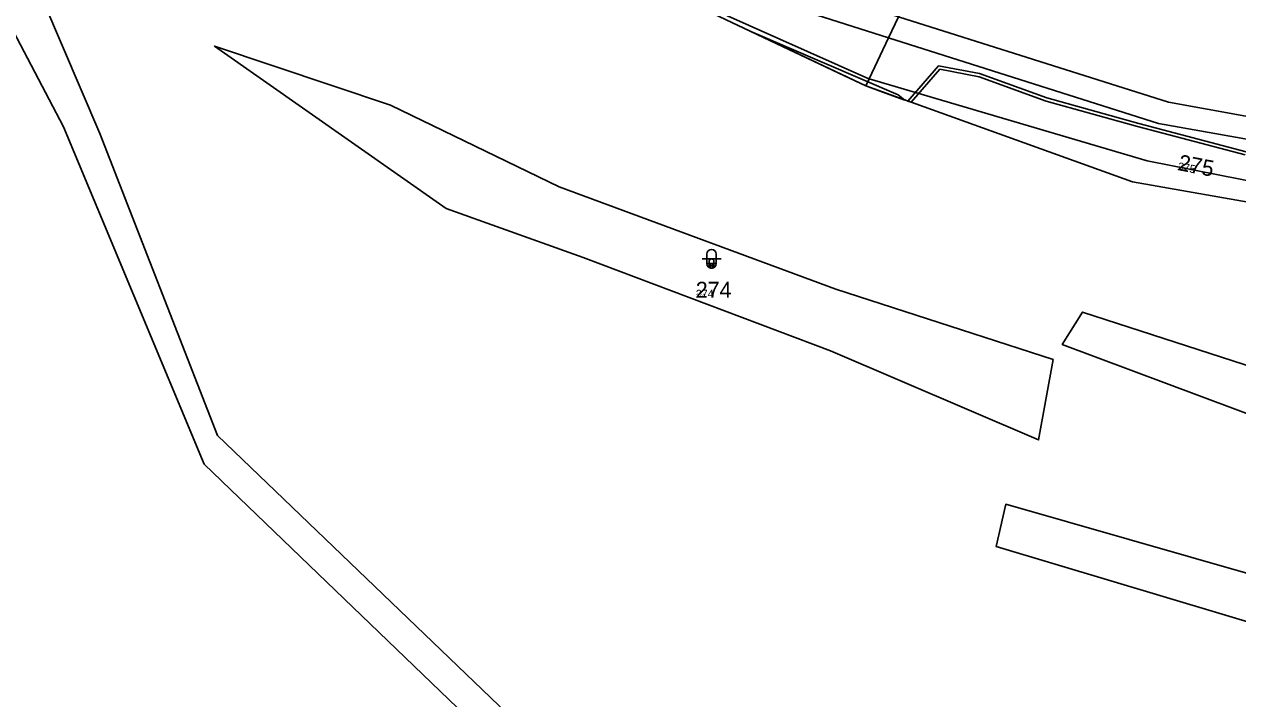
# Model space of a CAD drawing. Extents: x -759873 to -758487, y -975024 to -973516.
# Drawn here: x -758816.8 to -758688, y -974535.9 to -974464.3 of the extents above; entities that cross this region are included whole.
import ezdxf

# ---------------------------------------------------------------- set-up
doc = ezdxf.new("R2010")
doc.units = 0
for name, color, linetype in [('KAT_02_hranice parcel', 7, 'Continuous'), ('KAT_03_1000_čísla parcelní', 7, 'Continuous'), ('KAT_03_250_čísla parcelní', 7, 'Continuous'), ('KAT_03_500_čísla parcelní', 7, 'Continuous'), ('KAT_04_vnitřní kresba', 7, 'Continuous'), ('KAT_05_1000_značky kultur', 7, 'Continuous'), ('KAT_05_250_značky kultur', 7, 'Continuous'), ('KAT_05_500_značky kultur', 7, 'Continuous'), ('KAT_10_věcná břemena', 7, 'Continuous'), ('KAT_14_plocha_pozemek', 7, 'Continuous')]:
    doc.layers.add(name, color=color, linetype=linetype)

msp = doc.modelspace()

# ---------------------------------------------------------------- linework, layer by layer
at = {"layer": 'KAT_02_hranice parcel'}
for points in [[(-758697.83, -974596.44), (-758723.53, -974581.66), (-758758.5, -974544.23), (-758796.32, -974507.97), (-758808.82, -974475.92), (-758814.76, -974462.01), (-758845.88, -974422.17), (-758854.49, -974404.19), (-758863.43, -974395.34), (-758883.13, -974381.25), (-758920.39, -974363.49)], [(-758920.39, -974363.49), (-758901.31, -974364.72), (-758886.55, -974368.01), (-758862.06, -974374.57), (-758847.81, -974380.27), (-758833.47, -974388.69), (-758822.73, -974398.57), (-758783.72, -974438.99), (-758767.08, -974450.68), (-758750.74, -974459.82), (-758727.47, -974470.86)], [(-758867.55, -974396.24), (-758858.57, -974407.31), (-758849.06, -974423.37), (-758818.74, -974463.59), (-758812.66, -974475.2), (-758797.73, -974511.01), (-758760.58, -974546.71), (-758726.38, -974585.65), (-758699.89, -974599.55)], [(-758727.47, -974470.86), (-758727.11, -974470.1), (-758725.04, -974465.74), (-758723.99, -974463.52)], [(-758597.31, -974492.42), (-758602.67, -974491.26), (-758657.21, -974479.48), (-758695.33, -974472.59), (-758723.99, -974463.52)], [(-758707.56, -974499.9), (-758730.64, -974492.42), (-758760.03, -974481.56), (-758777.95, -974472.89), (-758796.63, -974466.63), (-758772.04, -974483.87), (-758757.47, -974489.08), (-758731.23, -974498.98), (-758709.11, -974508.43), (-758707.56, -974499.9)], [(-758727.47, -974470.86), (-758699.13, -974481.04), (-758639.55, -974491.51)], [(-758639.55, -974491.51), (-758640.63, -974495.69), (-758602.31, -974501.43), (-758606.38, -974521.63), (-758650.34, -974512.39), (-758704.47, -974494.86), (-758706.61, -974498.3), (-758651.5, -974518.9), (-758608.18, -974528.3), (-758611.55, -974539.9), (-758642.99, -974531.28), (-758653.42, -974532.21), (-758712.61, -974515.26), (-758713.61, -974519.76), (-758648.23, -974539.32), (-758612.86, -974545.85), (-758615.06, -974562.12), (-758700.21, -974537.79), (-758703.41, -974545.99), (-758657.92, -974561.88), (-758653.86, -974564.39)]]:
    msp.add_lwpolyline(points, dxfattribs=at)
at = {"layer": 'KAT_04_vnitřní kresba'}
for p, q in [((-758741.35, -974460.56), (-758725.04, -974465.74)), ((-758743.1, -974463), (-758727.14, -974470.09)), ((-758725.04, -974465.74), (-758696.4, -974474.85)), ((-758727.14, -974470.09), (-758727.11, -974470.1)), ((-758727.11, -974470.1), (-758697.6, -974478.8)), ((-758696.4, -974474.85), (-758597.31, -974492.42)), ((-758697.6, -974478.8), (-758599.61, -974498.06))]:
    msp.add_line(p, q, dxfattribs=at)
at = {"layer": 'KAT_05_1000_značky kultur'}
for p, q in [((-758744.84, -974489.21), (-758742.84, -974489.21)), ((-758744.34, -974488.71), (-758744.34, -974489.71)), ((-758743.34, -974489.71), (-758743.34, -974488.71))]:
    msp.add_line(p, q, dxfattribs=at)
for centre, start, end in [((-758743.84, -974488.71), 0, 180), ((-758743.84, -974489.71), 180, 359.9879)]:
    msp.add_arc(centre, 0.5, start, end, dxfattribs=at)
at = {"layer": 'KAT_05_250_značky kultur'}
for p, q in [((-758744.09, -974489.96), (-758743.59, -974489.96)), ((-758743.97, -974489.84), (-758743.97, -974490.09)), ((-758743.71, -974490.09), (-758743.71, -974489.84))]:
    msp.add_line(p, q, dxfattribs=at)
for centre, start, end in [((-758743.84, -974489.84), 0, 180), ((-758743.84, -974490.09), 180, 359.9879)]:
    msp.add_arc(centre, 0.125, start, end, dxfattribs=at)
at = {"layer": 'KAT_05_500_značky kultur'}
for p, q in [((-758744.09, -974489.46), (-758744.09, -974489.96)), ((-758743.59, -974489.96), (-758743.59, -974489.46)), ((-758744.34, -974489.71), (-758743.34, -974489.71))]:
    msp.add_line(p, q, dxfattribs=at)
for centre, start, end in [((-758743.84, -974489.46), 0, 180), ((-758743.84, -974489.96), 180, 359.9879)]:
    msp.add_arc(centre, 0.25, start, end, dxfattribs=at)
at = {"layer": 'KAT_10_věcná břemena'}
msp.add_lwpolyline([(-758739.67, -974465.07), (-758730.32, -974469.51), (-758727.47, -974470.86), (-758725.39, -974471.61), (-758723.31, -974472.35), (-758724.02, -974471.81)], close=True, dxfattribs=at)
msp.add_lwpolyline([(-758687.09, -974477.84), (-758698.47, -974474.83), (-758708.25, -974472.12), (-758715.39, -974469.54), (-758719.74, -974468.71), (-758723, -974472.46), (-758722.65, -974472.59), (-758719.6, -974469.09), (-758715.43, -974469.88), (-758708.31, -974472.48), (-758698.63, -974475.15), (-758687.19, -974478.18)], dxfattribs=at)
at = {"layer": 'KAT_14_plocha_pozemek'}
for points in [[(-758697.83, -974596.44), (-758723.53, -974581.66), (-758758.5, -974544.23), (-758796.32, -974507.97), (-758808.82, -974475.92), (-758814.76, -974462.01), (-758845.88, -974422.17), (-758854.49, -974404.19), (-758863.43, -974395.34), (-758883.13, -974381.25), (-758920.39, -974363.49), (-758930.04, -974363.17), (-758881.44, -974386.63), (-758867.55, -974396.24), (-758858.57, -974407.31), (-758849.06, -974423.37), (-758818.74, -974463.59), (-758812.66, -974475.2), (-758797.73, -974511.01), (-758760.58, -974546.71), (-758726.38, -974585.65), (-758699.89, -974599.55)], [(-758626.75, -974464.95), (-758627.86, -974462.19), (-758640.39, -974457.49), (-758682.5, -974452.45), (-758718.12, -974451.24), (-758723.99, -974463.52), (-758695.33, -974472.59), (-758657.21, -974479.48), (-758602.67, -974491.26), (-758597.31, -974492.42), (-758588.63, -974471.08), (-758595.89, -974469.25)], [(-758597.31, -974492.42), (-758602.67, -974491.26), (-758657.21, -974479.48), (-758695.33, -974472.59), (-758723.99, -974463.52), (-758725.04, -974465.74), (-758727.11, -974470.1), (-758727.47, -974470.86), (-758699.13, -974481.04), (-758639.55, -974491.51), (-758604.44, -974497.84), (-758599.61, -974498.06)], [(-758707.56, -974499.9), (-758730.64, -974492.42), (-758760.03, -974481.56), (-758777.95, -974472.89), (-758796.63, -974466.63), (-758772.04, -974483.87), (-758757.47, -974489.08), (-758731.23, -974498.98), (-758709.11, -974508.43)], [(-758707.56, -974499.9), (-758709.11, -974508.43), (-758731.23, -974498.98), (-758757.47, -974489.08), (-758772.04, -974483.87), (-758796.63, -974466.63), (-758777.95, -974472.89), (-758760.03, -974481.56), (-758730.64, -974492.42)]]:
    msp.add_lwpolyline(points, close=True, dxfattribs=at)
for points in [[(-758760.58, -974546.71), (-758797.73, -974511.01), (-758812.66, -974475.2), (-758818.74, -974463.59), (-758849.06, -974423.37), (-758858.57, -974407.31), (-758867.55, -974396.24), (-758911.81, -974379.4), (-758952.35, -974369.35), (-758971.41, -974365.53), (-758992.93, -974364.06), (-759006.26, -974363.99)], [(-758822.73, -974398.57), (-758783.72, -974438.99), (-758767.08, -974450.68), (-758750.74, -974459.82), (-758727.47, -974470.86), (-758727.11, -974470.1), (-758725.04, -974465.74), (-758723.99, -974463.52), (-758736.81, -974459.41), (-758751.44, -974452.92), (-758769.93, -974440.57), (-758773.37, -974436.18), (-758778.07, -974429.36), (-758781.33, -974429.8), (-758792.35, -974418.84), (-758810.18, -974401.15), (-758829.43, -974382.81)], [(-758648.23, -974539.32), (-758713.61, -974519.76), (-758712.61, -974515.26), (-758653.42, -974532.21), (-758642.99, -974531.28), (-758611.55, -974539.9), (-758608.18, -974528.3), (-758651.5, -974518.9), (-758706.61, -974498.3), (-758704.47, -974494.86), (-758650.34, -974512.39), (-758606.38, -974521.63), (-758602.31, -974501.43), (-758640.63, -974495.69), (-758639.55, -974491.51), (-758699.13, -974481.04), (-758727.47, -974470.86), (-758750.74, -974459.82), (-758767.08, -974450.68), (-758783.72, -974438.99), (-758822.73, -974398.57)], [(-758845.88, -974422.17), (-758814.76, -974462.01), (-758808.82, -974475.92), (-758796.32, -974507.97), (-758758.5, -974544.23)], [(-758607.97, -974566.39), (-758601.73, -974523.85), (-758599.61, -974498.06), (-758604.44, -974497.84), (-758639.55, -974491.51), (-758640.63, -974495.69), (-758602.31, -974501.43), (-758606.38, -974521.63), (-758650.34, -974512.39), (-758704.47, -974494.86), (-758706.61, -974498.3), (-758651.5, -974518.9), (-758608.18, -974528.3), (-758611.55, -974539.9), (-758642.99, -974531.28), (-758653.42, -974532.21), (-758712.61, -974515.26), (-758713.61, -974519.76), (-758648.23, -974539.32)]]:
    msp.add_lwpolyline(points, dxfattribs=at)

# ---------------------------------------------------------------- texts
at = {"layer": 'KAT_03_1000_čísla parcelní'}
msp.add_text('275', height=1.7, rotation=349, dxfattribs=at).set_placement((-758694.4, -974479.78))
msp.add_text('274', height=1.7, dxfattribs=at).set_placement((-758745.52, -974493.35))
at = {"layer": 'KAT_03_250_čísla parcelní'}
msp.add_text('275', height=0.425, rotation=349, dxfattribs=at).set_placement((-758694.4, -974479.78))
msp.add_text('274', height=0.425, dxfattribs=at).set_placement((-758745.52, -974493.35))
at = {"layer": 'KAT_03_500_čísla parcelní'}
msp.add_text('275', height=0.85, rotation=349, dxfattribs=at).set_placement((-758694.4, -974479.78))
msp.add_text('274', height=0.85, dxfattribs=at).set_placement((-758745.52, -974493.35))

doc.saveas('drawing.dxf')
